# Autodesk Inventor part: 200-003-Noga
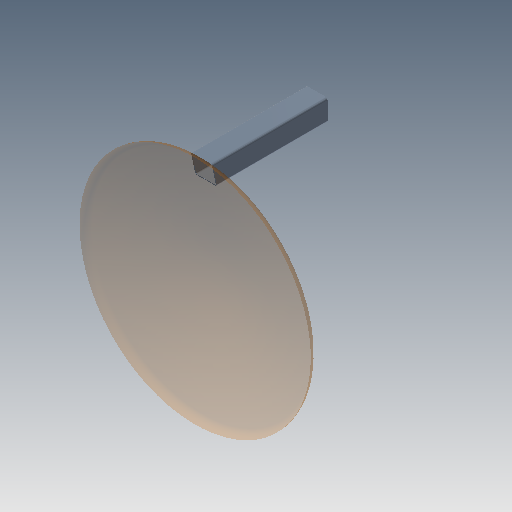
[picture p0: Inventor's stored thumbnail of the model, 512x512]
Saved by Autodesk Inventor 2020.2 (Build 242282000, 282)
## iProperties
Created: 2014-03
Part Number: 200-003-Noga
Material: Stal
Document SubType Name: Modeling
Designer: F.Stasiak
Density: 7.85 g/cm^3
Appearance: Stalowoniebieska
Mass: 16727.8 g
Surface Area: 5418.6 cm^2
Volume: 2130.93 cm^3
Catalog Web Link: www.expertbooks.pl
Manager: www.cadconsulting.pl
Company: Fabian Stasiak CAD Consulting
Author: F.Stasiak
Subject: Zbiór ćwiczeń. Autodesk Inventor 2020. Kurs Professional
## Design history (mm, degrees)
sketch "Szkic1"
  geometry: L1 (-75, 775)-(75, 775); L2 (75, 775)-(75, 625); L3 (75, 625)-(-75, 625); L4 (-75, 625)-(-75, 775); L5 (-75, 775)-(75, 625); L6 (75, 775)-(-75, 625); C1 r 800 at (0, 0) reference; 2 further points
  constraints: 12 end point, 2 midpoint, 2 parallel, 1 horizontal, 1 perpendicular
  dimensions: "d0" = 150 distance of L2.end L3.end; "d1" = 150 distance of L1.end L2.end; "d2" = 700 distance of point (0, 700) point (0, 0)
  node "Odniesienie1"
extrude "Wyciągnięcie proste2" new body sketch "Szkic1" distance "d7" = 850; taper "d8" = 0 deg
fillet "Zaokrąglenie2" dims "d9" = 15
feature "Skorupa2" dims "d10" = 6
feature "Powierzchnia6"
feature "Podział3"
node "Bryła2"
body "Srf9"
